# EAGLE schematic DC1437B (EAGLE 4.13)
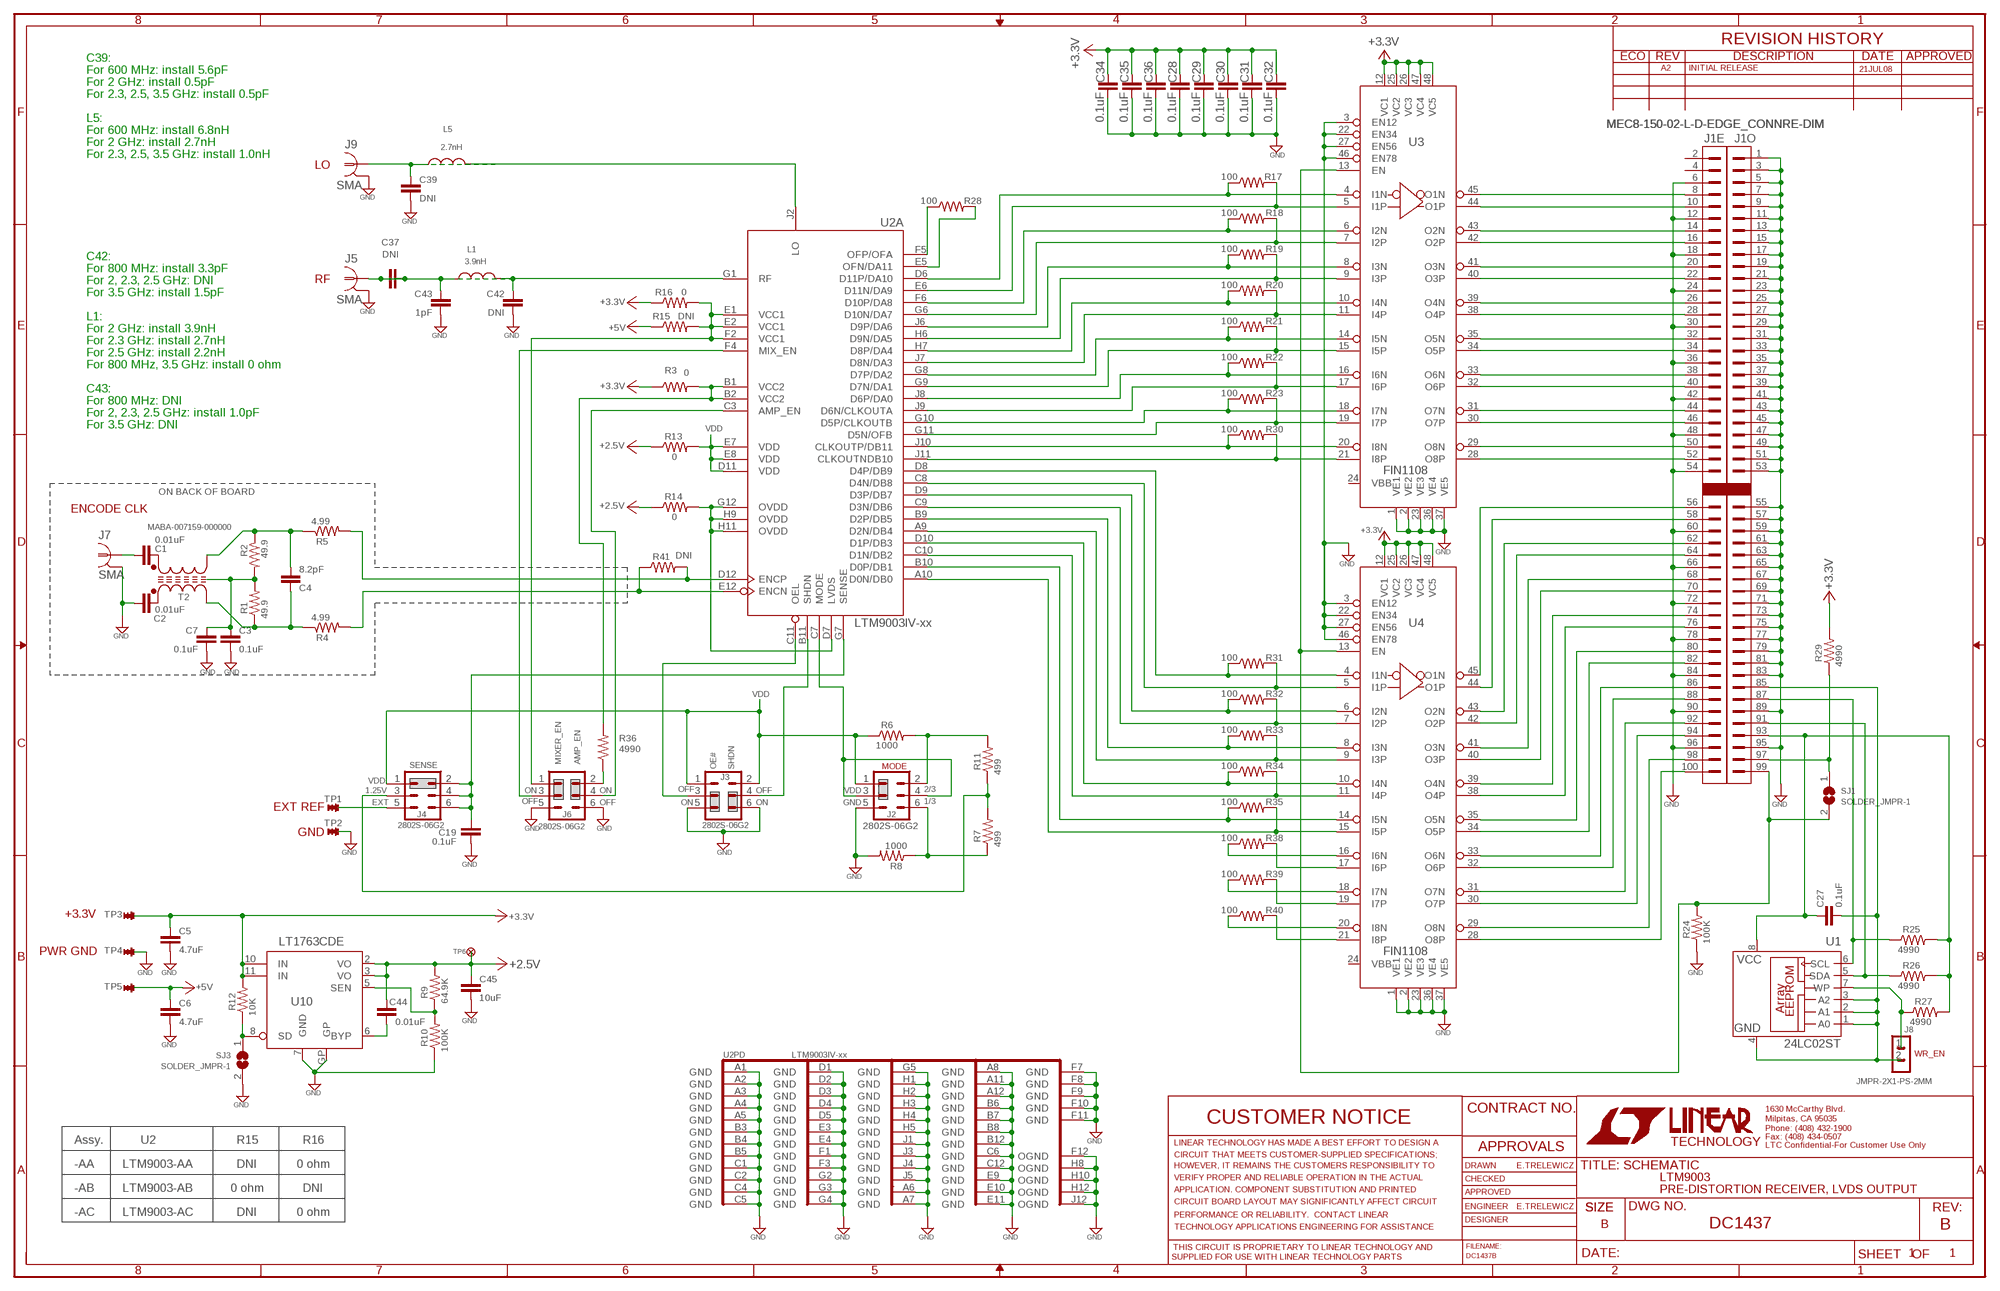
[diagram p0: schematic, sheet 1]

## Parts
C1  0.01uF  CAP-NP-SMT-C0402  [C0402]
C2  0.01uF  CAP-NP-SMT-C0402  [C0402]
C3  0.1uF  CAP-NP-SMT-C0603  [C0603]
C4  8.2pF  CAP-NP-SMT-C0402  [C0402]
C5  4.7uF  CAP-NP-SMT-C0805  [C0805]
C6  4.7uF  CAP-NP-SMT-C0805  [C0805]
C7  0.1uF  CAP-NP-SMT-C0603  [C0603]
C19  0.1uF  CAP-NP-SMT-C0402  [C0402]
C27  0.1uF  CAP-NP-SMT-C0402  [C0402]
C28  0.1uF  CAP-NP-SMT-C0402  [C0402]
C29  0.1uF  CAP-NP-SMT-C0402  [C0402]
C30  0.1uF  CAP-NP-SMT-C0402  [C0402]
C31  0.1uF  CAP-NP-SMT-C0402  [C0402]
C32  0.1uF  CAP-NP-SMT-C0402  [C0402]
C34  0.1uF  CAP-NP-SMT-C0402  [C0402]
C35  0.1uF  CAP-NP-SMT-C0402  [C0402]
C36  0.1uF  CAP-NP-SMT-C0402  [C0402]
C37  DNI  CAP-NP-SMT-C0402  [C0402]
C39  DNI  CAP-NP-SMT-C0402  [C0402]
C42  DNI  CAP-NP-SMT-C0402  [C0402]
C43  1pF  CAP-NP-SMT-C0402  [C0402]
C44  0.01uF  CAP-NP-SMT-C0402  [C0402]
C45  10uF  CAP-NP-SMT-C0805  [C0805]
J1  MEC8-150-02-L-D-EDGE_CONNRE-DIM  [MEC8-150-02-L-D-EDGE_CONN-NEW-ORIGIN]
J2  2802S-06G2  HDR-3X2-PS2MM  [HDR-3X2PS-2MM]
J3  2802S-06G2  HDR-3X2-PS2MM  [HDR-3X2PS-2MM]
J4  2802S-06G2  HDR-3X2-PS2MM  [HDR-3X2PS-2MM]
J5  SMA  RF_CONN-SMA-FEMALE-EDGE-MNT-GHZ  [SMA_FEMALE_EDGE_MNT_GHZ]
J6  2802S-06G2  HDR-3X2-PS2MM  [HDR-3X2PS-2MM]
J7  SMA  RF_CONN-SMA-FEMALE-EDGE-MNT  [SMA-FEMALE-EDGE-MNT]
J8  JMPR-2X1-PS-2MM  [HDR-2X1PS-2MM]
J9  SMA  RF_CONN-SMA-FEMALE-EDGE-MNT-GHZ  [SMA_FEMALE_EDGE_MNT_GHZ]
L1  3.9nH  IND-CER-SMT-0402  [L0402]
L5  2.7nH  IND-CER-SMT-0402  [L0402]
R1  49.9  RES-R0402  [R0402]
R2  49.9  RES-R0402  [R0402]
R3  0  RES-R0805  [R0805]
R4  4.99  RES-R0402  [R0402]
R5  4.99  RES-R0402  [R0402]
R6  1000  RES-R0603  [R0603]
R7  499  RES-R0603  [R0603]
R8  1000  RES-R0603  [R0603]
R9  64.9K  RES-R0402  [R0402]
R10  100K  RES-R0402  [R0402]
R11  499  RES-R0603  [R0603]
R12  10K  RES-R0402  [R0402]
R13  0  RES-R0805  [R0805]
R14  0  RES-R0805  [R0805]
R15  DNI  RES-R0805  [R0805]
R16  0  RES-R0805  [R0805]
R17  100  RES-R0201  [R0201]
R18  100  RES-R0201  [R0201]
R19  100  RES-R0201  [R0201]
R20  100  RES-R0201  [R0201]
R21  100  RES-R0201  [R0201]
R22  100  RES-R0201  [R0201]
R23  100  RES-R0201  [R0201]
R24  100K  RES-R0402  [R0402]
R25  4990  RES-R0402  [R0402]
R26  4990  RES-R0402  [R0402]
R27  4990  RES-R0402  [R0402]
R28  100  RES-R0201  [R0201]
R29  4990  RES-R0402  [R0402]
R30  100  RES-R0201  [R0201]
R31  100  RES-R0201  [R0201]
R32  100  RES-R0201  [R0201]
R33  100  RES-R0201  [R0201]
R34  100  RES-R0201  [R0201]
R35  100  RES-R0201  [R0201]
R36  4990  RES-R0402  [R0402]
R38  100  RES-R0201  [R0201]
R39  100  RES-R0201  [R0201]
R40  100  RES-R0201  [R0201]
R41  DNI  RES-R0201  [R0201]
SJ1  SOLDER_JMPR-1  [SJ1]
SJ3  SOLDER_JMPR-1  [SJ1]
T2  MABA-007159-000000  ETC1-1-13  [MACOM_ETC1-XFMR]
TP1  TURRET0.063  [TURRET_MILLMAX_2308-2]
TP2  TURRET0.063  [TURRET_MILLMAX_2308-2]
TP3  TURRET0.063  [TURRET_MILLMAX_2308-2]
TP4  TURRET0.063  [TURRET_MILLMAX_2308-2]
TP5  TURRET0.063  [TURRET_MILLMAX_2308-2]
TP6  TSTPNT25MIL  [VIA-25MIL]
U1  24LC02ST  [TSSOP8]
U2  LTM9003IV-xx  LTM9003  [LTM9003-RNDED]
U3  FIN1108  [TSSOP48]
U4  FIN1108  [TSSOP48]
U10  LT1763CDE  [DE12]

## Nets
+2.5V: C44.1 C45.1 R9.2 R13.1 R14.1 TP6.1 U10.2(VO) U10.3(VO)
+3.3V: C5.1 C28.1 C29.1 C30.1 C31.1 C32.1 C34.1 C35.1 C36.1 R3.1 R12.2 R16.1 R29.2 TP3.1 U3.12(VC1) U3.25(VC2) U3.26(VC3) U3.47(VC4) U3.48(VC5) U4.12(VC1) U4.25(VC2) U4.26(VC3) U4.47(VC4) U4.48(VC5) U10.10(IN) U10.11(IN)
+5V: C6.1 R15.1 TP5.1
AMP_EN: J6.4 U2.C3(A:AMP_EN)
ECCN: R4.2 R41.1 U2.E12(A:ENCN)
ENCP: R5.2 R41.2 U2.D12(A:ENCP)
EXT_REF: J4.5 TP1.1
GND: C2.1 C3.2 C5.2 C6.2 C7.2 C19.2 C28.2 C29.2 C30.2 C31.2 C32.2 C34.2 C35.2 C36.2 C39.2 C42.2 C43.2 C45.2 J1.1 J1.3 J1.5 J1.6 J1.7 J1.9 J1.11 J1.12 J1.13 J1.15 J1.17 J1.18 J1.19 J1.21 J1.23 J1.24 J1.25 J1.27 J1.29 J1.30 J1.31 J1.33 J1.35 J1.36 J1.37 J1.39 J1.41 J1.42 J1.43 J1.45 J1.47 J1.48 J1.49 J1.51 J1.53 J1.54 J1.55 J1.57 J1.59 J1.60 J1.61 J1.63 J1.65 J1.66 J1.67 J1.69 J1.71 J1.72 J1.73 J1.75 J1.77 J1.78 J1.79 J1.81 J1.83 J1.84 J1.89 J1.90 J1.95 J1.96 J2.5 J3.5 J3.6 J5.2(GND) J6.5 J6.6 J7.2(GND) J9.2(GND) R8.2 R10.1 R24.1 SJ3.2 TP2.1 TP4.1 U2.A1(PD:GND) U2.A2(PD:GND) U2.A3(PD:GND) U2.A4(PD:GND) U2.A5(PD:GND) U2.A6(PD:GND) U2.A7(PD:GND) U2.A8(PD:GND) U2.A11(PD:GND) U2.A12(PD:GND) U2.B3(PD:GND) U2.B4(PD:GND) U2.B5(PD:GND) U2.B6(PD:GND) U2.B7(PD:GND) U2.B8(PD:GND) U2.B12(PD:GND) U2.C1(PD:GND) U2.C2(PD:GND) U2.C4(PD:GND) U2.C5(PD:GND) U2.C6(PD:GND) U2.C12(PD:GND) U2.D1(PD:GND) U2.D2(PD:GND) U2.D3(PD:GND) U2.D4(PD:GND) U2.D5(PD:GND) U2.E3(PD:GND) U2.E4(PD:GND) U2.E9(PD:GND) U2.E10(PD:GND) U2.E11(PD:GND) U2.F1(PD:GND) U2.F3(PD:GND) U2.F7(PD:GND) U2.F8(PD:GND) U2.F9(PD:GND) U2.F10(PD:GND) U2.F11(PD:GND) U2.F12(PD:OGND) U2.G2(PD:GND) U2.G3(PD:GND) U2.G4(PD:GND) U2.G5(PD:GND) U2.H1(PD:GND) U2.H2(PD:GND) U2.H3(PD:GND) U2.H4(PD:GND) U2.H5(PD:GND) U2.H8(PD:OGND) U2.H10(PD:OGND) U2.H12(PD:OGND) U2.J1(PD:GND) U2.J3(PD:GND) U2.J4(PD:GND) U2.J5(PD:GND) U2.J12(PD:OGND) U3.1(VE1) U3.2(VE2) U3.3(EN12) U3.22(EN34) U3.23(VE3) U3.27(EN56) U3.36(VE4) U3.37(VE5) U3.46(EN78) U4.1(VE1) U4.2(VE2) U4.3(EN12) U4.22(EN34) U4.23(VE3) U4.27(EN56) U4.36(VE4) U4.37(VE5) U4.46(EN78) U10.7(GND) U10.GP
GROM: C27.2 J1.85 J8.2 U1.1(A0) U1.2(A1) U1.3(A2) U1.4(GND)
LO: L5.2 U2.J2(A:LO)
MIX_EN: J6.3 U2.F4(A:MIX_EN)
MODE: J2.3 J2.4 U2.C7(A:MODE)
N$1: C1.2 T2.4
N$2: C2.2 T2.5
N$3: C3.1 C7.1 R1.2 R2.2
N$4: C1.1 J7.1
N$5: R17.1 U2.D6(A:D11P/DA10) U3.4(I1N)
N$6: C4.2 R2.1 R5.1 T2.3
N$7: C4.1 R1.1 R4.1 T2.1
N$8: J6.2 R36.1
N$9: C37.1 C37.2 C43.1 J5.1 L1.1
N$10: R12.1 SJ3.1 U10.8(SD)
N$11: J2.6 R7.1 R8.1
N$12: R28.1 U2.F5(A:OFP/OFA)
N$13: C39.1 J9.1 L5.1
N$14: J1.10 U3.44(O1P)
N$15: J2.2 R6.2 R11.2
N$16: J1.56 U4.45(O1N)
N$17: J1.8 U3.45(O1N)
N$18: J1.46 U3.30(O7P)
N$19: J1.40 U3.32(O6P)
N$20: J1.38 U3.33(O6N)
N$21: J1.34 U3.34(O5P)
N$22: J1.32 U3.35(O5N)
N$23: J1.28 U3.38(O4P)
N$24: J1.26 U3.39(O4N)
N$25: J1.22 U3.40(O3P)
N$26: J1.20 U3.41(O3N)
N$27: J1.16 U3.42(O2P)
N$28: J1.14 U3.43(O2N)
N$29: J1.58 U4.44(O1P)
N$30: R9.1 R10.2 U10.5(SEN)
N$31: J1.62 U4.43(O2N)
N$32: J1.64 U4.42(O2P)
N$33: J1.44 U3.31(O7N)
N$34: J1.68 U4.41(O3N)
N$35: J1.70 U4.40(O3P)
N$36: C44.2 U10.6(BYP)
N$37: J1.74 U4.39(O4N)
N$38: J1.76 U4.38(O4P)
N$39: J1.80 U4.35(O5N)
N$40: J1.82 U4.34(O5P)
N$41: J1.86 U4.33(O6N)
N$42: J1.88 U4.32(O6P)
N$43: J1.92 U4.31(O7N)
N$44: J1.94 U4.30(O7P)
N$45: J1.98 U4.29(O8N)
N$46: J1.100 U4.28(O8P)
N$47: J8.1 R27.1 U1.7(WP)
N$49: R28.2 U2.E5(A:OFN/DA11)
N$50: J1.50 U3.29(O8N)
N$51: J1.52 U3.28(O8P)
N$60: R30.2 U2.J11(A:CLKOUTNDB10) U3.21(I8P)
N$63: R30.1 U2.J10(A:CLKOUTP/DB11) U3.20(I8N)
N$65: R17.2 U2.E6(A:D11N/DA9) U3.5(I1P)
N$66: R18.1 U2.F6(A:D10P/DA8) U3.6(I2N)
N$68: R18.2 U2.G6(A:D10N/DA7) U3.7(I2P)
N$69: R34.1 U2.D10(A:D1P/DB3) U4.10(I4N)
N$70: R20.1 U2.H7(A:D8P/DA4) U3.10(I4N)
N$71: R35.1 U2.B10(A:D0P/DB1) U4.14(I5N)
N$73: R31.1 U2.D8(A:D4P/DB9) U4.4(I1N)
N$74: R21.1 U2.G8(A:D7P/DA2) U3.14(I5N)
N$75: R35.2 U2.A10(A:D0N/DB0) U4.15(I5P)
N$76: R22.1 U2.J8(A:D6P/DA0) U3.16(I6N)
N$77: R22.2 U2.J9(A:D6N/CLKOUTA) U3.17(I6P)
N$78: R23.1 U2.G10(A:D5P/CLKOUTB) U3.18(I7N)
N$81: R31.2 U2.C8(A:D4N/DB8) U4.5(I1P)
N$86: R39.2 U4.19(I7P)
N$88: R38.1 U4.16(I6N)
N$93: R23.2 U2.G11(A:D5N/OFB) U3.19(I7P)
N$95: R19.2 U2.H6(A:D9N/DA5) U3.9(I3P)
N$99: R20.2 U2.J7(A:D8N/DA3) U3.11(I4P)
N$100: R21.2 U2.G9(A:D7N/DA1) U3.15(I5P)
N$101: R19.1 U2.J6(A:D9P/DA6) U3.8(I3N)
N$105: R32.1 U2.D9(A:D3P/DB7) U4.6(I2N)
N$106: R32.2 U2.C9(A:D3N/DB6) U4.7(I2P)
N$107: R33.1 U2.B9(A:D2P/DB5) U4.8(I3N)
N$108: R33.2 U2.A9(A:D2N/DB4) U4.9(I3P)
N$109: R34.2 U2.C10(A:D1N/DB2) U4.11(I4P)
N$114: R38.2 U4.17(I6P)
N$124: R40.2 U4.21(I8P)
N$126: R39.1 U4.18(I7N)
N$131: R40.1 U4.20(I8N)
OEL: J3.3 U2.C11(A:OEL)
OUT-ENABLE: J1.99 R24.2 SJ1.2 U3.13(EN) U4.13(EN)
OVDD: R14.2 U2.D7(A:LVDS) U2.G12(A:OVDD) U2.H9(A:OVDD) U2.H11(A:OVDD)
PWR-ON: J1.97 R29.1 SJ1.1
RF: C42.1 L1.2 U2.G1(A:RF)
SCL: J1.87 R25.1 U1.6(SCL)
SDA: J1.91 R26.1 U1.5(SDA)
SENSE: C19.1 J4.2 J4.4 J4.6 U2.G7(A:SENSE)
SHDN: J3.4 U2.B11(A:SHDN)
VCC1: J6.1 R15.2 R16.2 U2.E1(A:VCC1) U2.E2(A:VCC1) U2.F2(A:VCC1)
VCC2: R3.2 R36.2 U2.B1(A:VCC2) U2.B2(A:VCC2)
VCM: J4.3 R7.2 R11.1
VDD: J2.1 J3.1 J3.2 J4.1 R6.1 R13.2 U2.D11(A:VDD) U2.E7(A:VDD) U2.E8(A:VDD)
VROM: C27.1 J1.93 R25.2 R26.2 R27.2 U1.8(VCC)
Unconnected: J1.2 J1.4 U3.24(VBB) U4.24(VBB)

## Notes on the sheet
- C39:
- A2 | INITIAL RELEASE | 21JUL08
- For 600 MHz: install 5.6pF
- For 2 GHz: install 0.5pF
- For 2.3, 2.5, 3.5 GHz: install 0.5pF
- L5:
- For 600 MHz: install 6.8nH
- For 2 GHz: install 2.7nH
- For 2.3, 2.5, 3.5 GHz: install 1.0nH
- LO
- C42:
- For 800 MHz: install 3.3pF
- For 2, 2.3, 2.5 GHz: DNI | RF
- For 3.5 GHz: install 1.5pF
- L1:
- For 2 GHz: install 3.9nH
- For 2.3 GHz: install 2.7nH
- For 2.5 GHz: install 2.2nH
- For 800 MHz, 3.5 GHz: install 0 ohm
- C43:
- For 800 MHz: DNI
- For 2, 2.3, 2.5 GHz: install 1.0pF
- For 3.5 GHz: DNI
- ON BACK OF BOARD
- ENCODE CLK
- MIXER_EN | AMP_EN
- SENSE | OE# | SHDN | MODE
- VDD
- 1.25V | ON | ON | OFF | OFF | VDD | 2/3
- EXT | OFF | OFF | ON | ON | GND | 1/3
- EXT REF
- GND
- +3.3V
- PWR GND
- WR_EN
- Assy. | U2 | R15 | R16
- -AA | LTM9003-AA | DNI | 0 ohm | E.TRELEWICZ
- LTM9003
- -AB | LTM9003-AB | 0 ohm | DNI | PRE-DISTORTION RECEIVER, LVDS OUTPUT
- E.TRELEWICZ
- -AC | LTM9003-AC | DNI | 0 ohm
- B | DC1437 | B
- 1 | 1

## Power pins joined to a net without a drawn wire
GND: J5.3(GND) J5.4(GND) J5.5(GND) J7.3(GND) J7.4(GND) J7.5(GND) J9.3(GND) J9.4(GND) J9.5(GND)

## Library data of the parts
C1-C7 C19 C27-C32 C34-C37 C39 C42-C45 = LTDB_Passives:CAP-NP-SMT-: Capacitor; Non-polar; SMT
J1 = LTDB_Connectors:MEC8-150-02-L-D-EDGE_CONN
J2-J4 J6 = LTDB_Connectors:HDR-3X2-PS: Header 3x2 Pin, Straight
J5 J7 J9 = LTDB_Connectors:RF_CONN-: BNC CONNECTOR M/A COM www.macom.com distributor Farnell 149-452
J8 = LTDB_Connectors:JMPR-2X1-PS?: Header, 2x1, 2mm
L1 L5 = LTDB_Passives:IND-CER-SMT-: Inductor,Ceramic,SMT
R1-R36 R38-R41 = LTDB_Passives:RES-: Resistor; GP
SJ1 SJ3 = LTDB_Connectors:SOLDER_JMPR-1
T2 = LTDB_Passives:ETC1-1-13: Balun 1:1, SMT, MaCom
TP1-TP5 = LTDB_Connectors:TURRET: Turret
TP6 = LTDB_Connectors:TSTPNT?
U1 = LTDB_ICs:24*?: I2C SEEP Memory
U2 = LTDB_Linear_Parts:LTM9003: Pre-distortion Receiver Module
U3 U4 = LTDB_ICs:FIN1108*: REPEATER,OCTAL,LVDS
U10 = LTDB_Linear_Parts:LT1763CDE: LDO, SMT, DFN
